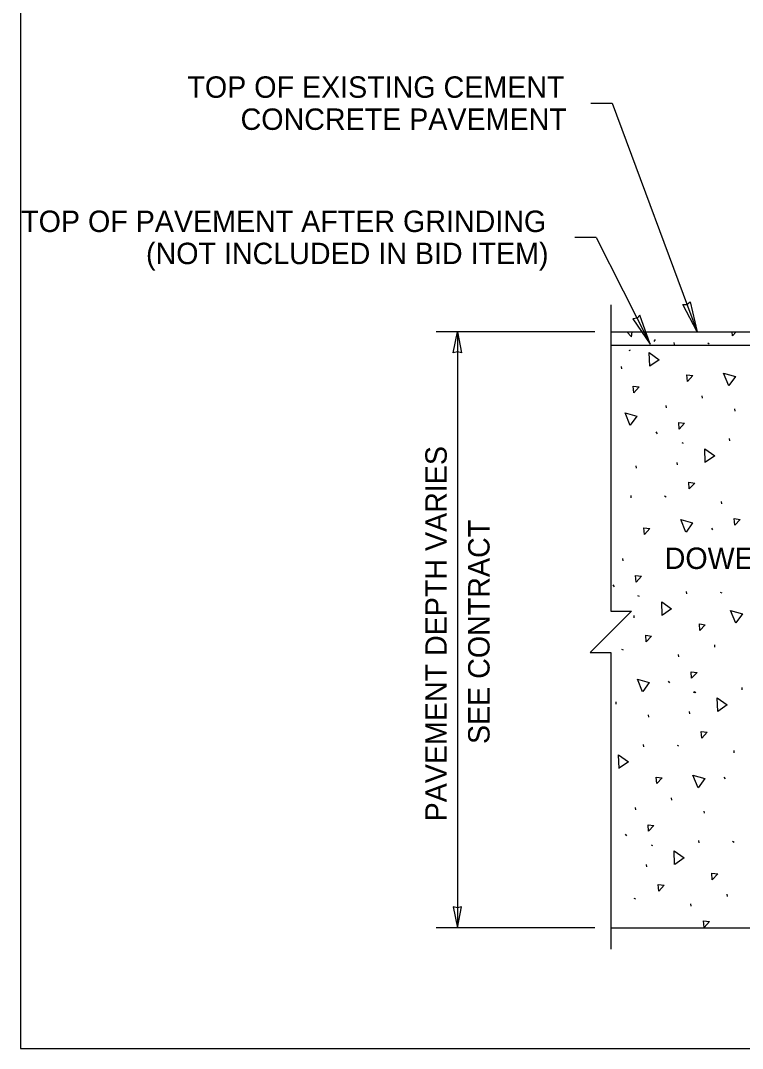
# Model space of a CAD drawing. Extents: x 99862 to 104211, y 98939 to 105076.
# Drawn here: x 99862 to 100401, y 103000 to 103768 of the extents above; entities that cross this region are included whole.
import ezdxf

# ---------------------------------------------------------------- set-up
doc = ezdxf.new("R2010")
doc.units = 0
for name, color, linetype in [('Level 1', 7, 'Continuous'), ('Level 15', 7, 'Continuous'), ('Level 20', 7, 'Continuous'), ('Level 4', 7, 'Continuous'), ('Level 6', 7, 'Continuous'), ('Level 60', 7, 'Continuous')]:
    doc.layers.add(name, color=color, linetype=linetype)

msp = doc.modelspace()

# ---------------------------------------------------------------- linework, layer by layer
at = {"layer": 'Level 1'}
for p, q in [((100303.06, 103535.25), (100514.84, 103535.25)), ((100303.06, 103089.64), (100883.88, 103089.64))]:
    msp.add_line(p, q, dxfattribs=at)
msp.add_lwpolyline([(99862, 102999.5), (103151, 102999.5), (103151, 105075.5), (99862, 105075.5)], close=True, dxfattribs=at)
msp.add_lwpolyline([(100303.06, 103555.25), (100303.06, 103326.36), (100318.54, 103326.36), (100287.57, 103295.38), (100303.06, 103295.38), (100303.06, 103073.64)], dxfattribs=at)
at = {"layer": 'Level 15'}
for p, q in [((100288.1, 103706.14), (100304.1, 103706.14)), ((100292.17, 103605.8), (100276.17, 103605.8)), ((100291.06, 103535.25), (100172.41, 103535.25)), ((100188.41, 103535.25), (100188.41, 103089.69)), ((100291.06, 103089.69), (100172.41, 103089.69))]:
    msp.add_line(p, q, dxfattribs=at)
for points in [[(100304.1, 103706.14), (100367.46, 103535.17)], [(100292.17, 103605.8), (100332.39, 103525.85)]]:
    msp.add_lwpolyline(points, dxfattribs=at)
for points in [[(100367.46, 103535.17), (100356.73, 103555.54), (100359.89, 103555.58), (100362.32, 103557.61)], [(100332.39, 103525.85), (100324.8, 103547.59), (100322.61, 103545.3), (100319.46, 103544.91)], [(100188.41, 103535.25), (100191.49, 103519.53), (100188.41, 103520.26), (100185.33, 103519.53)], [(100188.41, 103089.69), (100191.49, 103105.41), (100188.41, 103104.69), (100185.33, 103105.41)]]:
    msp.add_lwpolyline(points, close=True, dxfattribs=at)
at = {"layer": 'Level 4'}
for p, q in [((100336.06, 103529.33), (100335.1, 103528.04)), ((100317.49, 103521.42), (100316.34, 103520.85)), ((100350.49, 103525.59), (100350.3, 103527.32)), ((100375.4, 103526.84), (100376.54, 103526.27)), ((100311.22, 103507.63), (100311.04, 103509.37)), ((100371.5, 103485.63), (100371.32, 103487.37)), ((100344.48, 103478.44), (100344.3, 103480.18)), ((100395.8, 103475.87), (100395.62, 103477.61)), ((100336.63, 103460.34), (100337.58, 103459.05)), ((100356.01, 103452.43), (100357.16, 103451.86)), ((100391.97, 103453.74), (100391.78, 103455.48)), ((100352.7, 103435.78), (100352.52, 103437.52)), ((100322.12, 103433.33), (100321.94, 103435.07)), ((100318.29, 103411.2), (100318.11, 103412.94)), ((100343.2, 103412.46), (100344.35, 103411.89)), ((100385.97, 103406.59), (100385.78, 103408.33)), ((100378.11, 103388.49), (100379.06, 103387.2)), ((100312.29, 103364.05), (100312.1, 103365.79)), ((100304.43, 103345.96), (100305.38, 103344.66)), ((100323, 103338.04), (100324.15, 103337.47)), ((100359.77, 103339.35), (100359.59, 103341.09)), ((100384.68, 103340.61), (100385.83, 103340.04)), ((100320.51, 103321.4), (100320.32, 103323.14)), ((100380.79, 103299.4), (100380.61, 103301.14)), ((100311, 103298.07), (100312.15, 103297.5)), ((100353.77, 103292.2), (100353.59, 103293.94)), ((100345.91, 103274.11), (100346.86, 103272.81)), ((100401.25, 103267.5), (100401.07, 103269.24)), ((100364.48, 103266.19), (100365.63, 103265.62)), ((100365.3, 103266.2), (100366.45, 103265.63)), ((100307.11, 103256.86), (100306.93, 103258.6)), ((100331.41, 103247.1), (100331.23, 103248.84)), ((100361.99, 103249.55), (100361.8, 103251.29)), ((100327.58, 103224.97), (100327.39, 103226.71)), ((100352.49, 103226.22), (100353.63, 103225.65)), ((100395.25, 103220.36), (100395.07, 103222.1)), ((100387.39, 103202.26), (100388.35, 103200.96)), ((100348.59, 103185.01), (100348.41, 103186.75)), ((100321.57, 103177.82), (100321.39, 103179.56)), ((100372.89, 103175.25), (100372.71, 103176.99)), ((100313.72, 103159.72), (100314.67, 103158.43)), ((100369.06, 103153.12), (100368.87, 103154.86)), ((100393.97, 103154.37), (100395.12, 103153.81)), ((100333.1, 103151.81), (100334.25, 103151.24)), ((100329.79, 103135.16), (100329.61, 103136.9)), ((100390.08, 103113.16), (100389.89, 103114.9)), ((100320.29, 103111.84), (100321.44, 103111.27)), ((100363.06, 103105.97), (100362.87, 103107.71))]:
    msp.add_line(p, q, dxfattribs=at)
for points in [[(100315.07, 103535.25), (100318.57, 103531.46)], [(100318.57, 103531.46), (100318.86, 103535.25)], [(100393.85, 103532.17), (100393.62, 103535.25)], [(100396.69, 103535.25), (100393.85, 103532.17)], [(100332.12, 103509.44), (100331.74, 103519.69), (100339.15, 103514.32), (100332.27, 103509.53)], [(100360.24, 103498.1), (100359.87, 103503.01), (100364.28, 103502.48), (100360.24, 103498.1)], [(100391.13, 103494.84), (100387.28, 103504.34), (100396.07, 103501.83), (100391.25, 103494.98)], [(100320.18, 103489.63), (100319.8, 103494.54), (100324.21, 103494.01), (100320.18, 103489.63)], [(100317.46, 103465.15), (100313.6, 103474.65), (100322.39, 103472.14), (100317.57, 103465.29)], [(100354.12, 103462.47), (100353.74, 103467.38), (100358.15, 103466.85), (100354.12, 103462.47)], [(100373.6, 103437.6), (100373.23, 103447.84), (100380.63, 103442.47), (100373.75, 103437.69)], [(100361.66, 103417.78), (100361.28, 103422.69), (100365.69, 103422.16), (100361.66, 103417.78)], [(100359.17, 103385.32), (100355.32, 103394.81), (100364.11, 103392.3), (100359.29, 103385.45)], [(100395.6, 103390.62), (100395.22, 103395.53), (100399.63, 103395), (100395.6, 103390.62)], [(100328.05, 103383.72), (100327.67, 103388.63), (100332.08, 103388.1), (100328.05, 103383.72)], [(100321.92, 103348.08), (100321.55, 103352.99), (100325.95, 103352.46), (100321.92, 103348.08)], [(100341.41, 103323.21), (100341.03, 103333.45), (100348.43, 103328.09), (100341.56, 103323.3)], [(100396.38, 103317.49), (100392.53, 103326.99), (100401.32, 103324.48), (100396.5, 103317.63)], [(100369.53, 103311.87), (100369.15, 103316.78), (100373.56, 103316.25), (100369.53, 103311.87)], [(100329.46, 103303.4), (100329.09, 103308.31), (100333.5, 103307.78), (100329.46, 103303.4)], [(100326.74, 103266.07), (100322.89, 103275.57), (100331.68, 103273.06), (100326.86, 103266.21)], [(100363.4, 103276.23), (100363.03, 103281.14), (100367.44, 103280.61), (100363.4, 103276.23)], [(100382.89, 103251.36), (100382.51, 103261.6), (100389.91, 103256.24), (100383.04, 103251.45)], [(100370.94, 103231.55), (100370.57, 103236.46), (100374.98, 103235.93), (100370.94, 103231.55)], [(100309.21, 103208.83), (100308.83, 103219.07), (100316.24, 103213.7), (100309.36, 103208.91)], [(100337.33, 103197.48), (100336.96, 103202.39), (100341.37, 103201.86), (100337.33, 103197.48)], [(100368.22, 103194.22), (100364.37, 103203.72), (100373.16, 103201.21), (100368.34, 103194.36)], [(100331.21, 103161.85), (100330.83, 103166.76), (100335.24, 103166.23), (100331.21, 103161.85)], [(100350.69, 103136.98), (100350.32, 103147.22), (100357.72, 103141.86), (100350.85, 103137.07)], [(100378.81, 103125.63), (100378.44, 103130.54), (100382.85, 103130.01), (100378.81, 103125.63)], [(100338.75, 103117.16), (100338.37, 103122.07), (100342.78, 103121.54), (100338.75, 103117.16)], [(100372.69, 103090), (100372.31, 103094.91), (100376.72, 103094.38), (100372.69, 103090)]]:
    msp.add_lwpolyline(points, dxfattribs=at)
at = {"layer": 'Level 6'}
msp.add_line((100303.06, 103525.25), (100883.88, 103525.25), dxfattribs=at)
at = {"layer": 'Level 60'}
msp.add_line((99862, 102999.5), (99862, 102999.5), dxfattribs=at)

# ---------------------------------------------------------------- texts
at = {"layer": 'Level 20'}
for s, p in [('TOP OF EXISTING CEMENT', (99986.65, 103710.14)), (' CONCRETE PAVEMENT', (100020.44, 103686.14)), ('DOWEL BAR', (100343.24, 103357.92))]:
    msp.add_text(s, height=16, dxfattribs=at).set_placement(p)
for s, rotation, p in [('TOP OF PAVEMENT AFTER GRINDING', 360, (99862.45, 103609.8)), ('(NOT INCLUDED IN BID ITEM)', 360, (99955.73, 103585.8)), ('PAVEMENT DEPTH VARIES', 90, (100180.41, 103169.24)), ('SEE CONTRACT', 90, (100212.41, 103227.05))]:
    msp.add_text(s, height=16, rotation=rotation, dxfattribs=at).set_placement(p)

doc.saveas('drawing.dxf')
